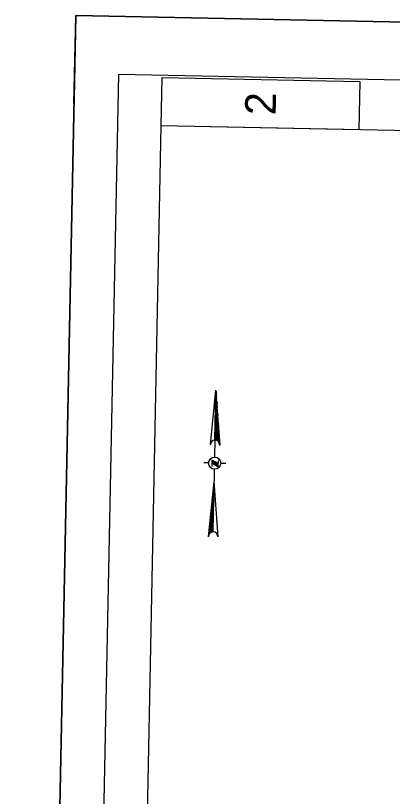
# Model space of a CAD drawing. Extents: x 345549 to 379569, y 127949 to 230467.
# Drawn here: x 345549 to 351986, y 217135 to 230467 of the extents above; entities that cross this region are included whole.
import ezdxf

# ---------------------------------------------------------------- set-up
doc = ezdxf.new("R2010")
doc.units = 0
for name, color, linetype in [('CA-TBLK', 7, 'Continuous'), ('P_RDWY_Text', 7, 'Continuous'), ('PLT_Sheet_Border', 7, 'Continuous'), ('PLT_Sheet_Info', 7, 'Continuous')]:
    doc.layers.add(name, color=color, linetype=linetype)

msp = doc.modelspace()

# ---------------------------------------------------------------- linework, layer by layer
at = {"layer": 'CA-TBLK'}
for p, q in [((348878, 223145), (348971, 224073)), ((348954, 223218), (348971, 224073)), ((348969, 223968), (348985, 223983)), ((348985, 224028), (348970, 224013)), ((348970, 224028), (348985, 224028)), ((348970, 224013), (348985, 224013)), ((348970, 223983), (348985, 223998)), ((348985, 223998), (348970, 223998)), ((348985, 223983), (348970, 223983)), ((349043, 223141), (348971, 224073)), ((348971, 224073), (348971, 224073)), ((348971, 224073), (348971, 224073)), ((348971, 224058), (348971, 224058)), ((348971, 224043), (348986, 224043)), ((348986, 224043), (348971, 224043)), ((348966, 223833), (348997, 223847)), ((348997, 223847), (348966, 223818)), ((348967, 223878), (348983, 223893)), ((348983, 223893), (348967, 223878)), ((348982, 223878), (348967, 223863)), ((348967, 223848), (348997, 223877)), ((348997, 223862), (348967, 223848)), ((348984, 223938), (348968, 223923)), ((348983, 223923), (348968, 223908)), ((348968, 223908), (348983, 223923)), ((348968, 223893), (348983, 223908)), ((348984, 223968), (348969, 223953)), ((348984, 223953), (348969, 223938)), ((348969, 223953), (348984, 223953)), ((348969, 223938), (348984, 223938)), ((348994, 223712), (348963, 223683)), ((348964, 223728), (348995, 223757)), ((348964, 223713), (348995, 223742)), ((348995, 223742), (348964, 223728)), ((348994, 223727), (348964, 223698)), ((348964, 223698), (348994, 223727)), ((348965, 223773), (348996, 223802)), ((348996, 223787), (348965, 223773)), ((348965, 223758), (348996, 223787)), ((348995, 223772), (348965, 223743)), ((348996, 223832), (348966, 223803)), ((348966, 223818), (348996, 223832)), ((348966, 223788), (348996, 223817)), ((348996, 223802), (348966, 223788)), ((348960, 223533), (349006, 223577)), ((348961, 223578), (349007, 223607)), ((349007, 223607), (348961, 223563)), ((349007, 223592), (348961, 223548)), ((348961, 223563), (349007, 223592)), ((348962, 223608), (349008, 223652)), ((349008, 223652), (348962, 223623)), ((348962, 223593), (349008, 223637)), ((349008, 223637), (348962, 223608)), ((349007, 223622), (348962, 223593)), ((348994, 223697), (348963, 223668)), ((348963, 223668), (348994, 223697)), ((349008, 223682), (348963, 223638)), ((348963, 223653), (349008, 223682)), ((348963, 223638), (349008, 223667)), ((348958, 223428), (349019, 223472)), ((349019, 223472), (348958, 223428)), ((348958, 223398), (349019, 223457)), ((349019, 223457), (348958, 223413)), ((349019, 223442), (348958, 223398)), ((349005, 223517), (348959, 223473)), ((348959, 223473), (349005, 223517)), ((349020, 223502), (348959, 223443)), ((348959, 223458), (349020, 223502)), ((348959, 223443), (349020, 223487)), ((348960, 223518), (349006, 223562)), ((349006, 223562), (348960, 223533)), ((348960, 223503), (349006, 223547)), ((349006, 223547), (348960, 223503)), ((349005, 223532), (348960, 223488)), ((349017, 223337), (348955, 223278)), ((348955, 223278), (349017, 223337)), ((349031, 223321), (348955, 223248)), ((348955, 223263), (349031, 223321)), ((348955, 223248), (349031, 223306)), ((348956, 223323), (349017, 223382)), ((348956, 223308), (349017, 223367)), ((349017, 223367), (348956, 223308)), ((349017, 223352), (348956, 223293)), ((349018, 223427), (348957, 223368)), ((348957, 223383), (349018, 223427)), ((349018, 223412), (348957, 223353)), ((348957, 223368), (349018, 223412)), ((348957, 223338), (349018, 223397)), ((349017, 223382), (348957, 223338)), ((348954, 223218), (348948, 222933)), ((348954, 223233), (349031, 223291)), ((349031, 223291), (348954, 223233)), ((349030, 223276), (348954, 223218)), ((348969, 223218), (349030, 223276)), ((349030, 223261), (348984, 223217)), ((348984, 223217), (349030, 223246)), ((349030, 223246), (348999, 223202)), ((349029, 223231), (348999, 223202)), ((348999, 223202), (349029, 223231)), ((349029, 223201), (349013, 223187)), ((349013, 223187), (349029, 223201)), ((349014, 223202), (349029, 223216)), ((349028, 223171), (349028, 223186)), ((349028, 223186), (349028, 223186)), ((349028, 223171), (349028, 223171)), ((349028, 223156), (349028, 223156)), ((349028, 223156), (349028, 223156)), ((349028, 223141), (349043, 223141)), ((348841, 222830), (348766, 222832)), ((348902, 222874), (348900, 222769)), ((348901, 222829), (348947, 222858)), ((348932, 222858), (348901, 222829)), ((348901, 222829), (348932, 222858)), ((348901, 222829), (349005, 222767)), ((348902, 222859), (348917, 222874)), ((348917, 222874), (348902, 222859)), ((348902, 222874), (348902, 222874)), ((349006, 222827), (348902, 222874)), ((348932, 222873), (348902, 222844)), ((348947, 222858), (348916, 222814)), ((348916, 222814), (348962, 222843)), ((348962, 222843), (348931, 222813)), ((348931, 222813), (348977, 222842)), ((348946, 222798), (348977, 222842)), ((348977, 222842), (348946, 222813)), ((349006, 222827), (348961, 222798)), ((348961, 222798), (348991, 222827)), ((348991, 222827), (348961, 222798)), ((348975, 222782), (349006, 222812)), ((349006, 222812), (348975, 222782)), ((348990, 222782), (349006, 222797)), ((349006, 222797), (348990, 222782)), ((349007, 222872), (349005, 222767)), ((349005, 222767), (349005, 222782)), ((349051, 222826), (349141, 222824)), ((348944, 222723), (348940, 222513)), ((348846, 221570), (348940, 222513)), ((348923, 221658), (348940, 222513)), ((349011, 221567), (348940, 222513)), ((348940, 222513), (348940, 222513)), ((348937, 222378), (348938, 222393)), ((348937, 222363), (348937, 222378)), ((348937, 222378), (348937, 222378)), ((348938, 222438), (348939, 222453)), ((348938, 222438), (348938, 222438)), ((348938, 222423), (348938, 222423)), ((348938, 222423), (348938, 222408)), ((348938, 222408), (348938, 222393)), ((348938, 222408), (348938, 222408)), ((348939, 222483), (348939, 222483)), ((348939, 222468), (348939, 222468)), ((348939, 222468), (348939, 222468)), ((348939, 222453), (348939, 222453)), ((348940, 222498), (348940, 222498)), ((348940, 222498), (348940, 222498)), ((348919, 222243), (348934, 222213)), ((348934, 222228), (348919, 222243)), ((348935, 222273), (348920, 222288)), ((348920, 222288), (348935, 222273)), ((348934, 222243), (348920, 222273)), ((348920, 222273), (348935, 222258)), ((348920, 222258), (348934, 222243)), ((348936, 222333), (348921, 222333)), ((348921, 222333), (348936, 222318)), ((348921, 222318), (348935, 222288)), ((348936, 222303), (348921, 222318)), ((348935, 222288), (348921, 222303)), ((348922, 222348), (348936, 222333)), ((348937, 222363), (348937, 222348)), ((348937, 222348), (348937, 222363)), ((348902, 222139), (348932, 222108)), ((348932, 222108), (348902, 222139)), ((348931, 222093), (348902, 222124)), ((348931, 222078), (348902, 222109)), ((348902, 222109), (348931, 222078)), ((348903, 222169), (348932, 222138)), ((348903, 222154), (348932, 222123)), ((348932, 222138), (348903, 222154)), ((348933, 222153), (348918, 222184)), ((348918, 222184), (348933, 222153)), ((348919, 222228), (348934, 222198)), ((348934, 222213), (348919, 222228)), ((348919, 222214), (348933, 222183)), ((348933, 222183), (348919, 222214)), ((348933, 222168), (348919, 222199)), ((348884, 221989), (348928, 221943)), ((348884, 221974), (348928, 221928)), ((348928, 221928), (348884, 221974)), ((348929, 221958), (348885, 222004)), ((348929, 221988), (348900, 222034)), ((348929, 221973), (348900, 222019)), ((348900, 222019), (348929, 221988)), ((348900, 222004), (348929, 221958)), ((348931, 222048), (348901, 222094)), ((348901, 222094), (348931, 222063)), ((348901, 222079), (348931, 222048)), ((348901, 222064), (348930, 222018)), ((348930, 222033), (348901, 222064)), ((348930, 222018), (348901, 222049)), ((348901, 222049), (348930, 222003)), ((348882, 221884), (348926, 221823)), ((348926, 221838), (348882, 221884)), ((348882, 221869), (348926, 221808)), ((348926, 221823), (348882, 221869)), ((348925, 221793), (348882, 221854)), ((348928, 221898), (348883, 221944)), ((348883, 221929), (348927, 221883)), ((348927, 221883), (348883, 221929)), ((348927, 221853), (348883, 221914)), ((348883, 221914), (348927, 221868)), ((348883, 221899), (348927, 221853)), ((348884, 221959), (348928, 221913)), ((348928, 221913), (348884, 221959)), ((348923, 221658), (348864, 221735)), ((348864, 221735), (348923, 221673)), ((348864, 221720), (348923, 221658)), ((348865, 221794), (348924, 221733)), ((348924, 221733), (348865, 221794)), ((348865, 221779), (348924, 221703)), ((348924, 221718), (348865, 221779)), ((348924, 221703), (348865, 221764)), ((348923, 221688), (348865, 221750)), ((348865, 221750), (348923, 221688)), ((348925, 221778), (348881, 221839)), ((348881, 221839), (348925, 221793)), ((348925, 221763), (348881, 221824)), ((348881, 221824), (348925, 221763)), ((348881, 221809), (348925, 221748)), ((348846, 221585), (348846, 221585)), ((348847, 221630), (348862, 221615)), ((348847, 221615), (348862, 221615)), ((348862, 221615), (348847, 221615)), ((348847, 221600), (348847, 221600)), ((348847, 221600), (348847, 221600)), ((348862, 221645), (348877, 221629)), ((348862, 221630), (348862, 221645)), ((348863, 221690), (348892, 221644)), ((348907, 221644), (348863, 221690)), ((348892, 221644), (348863, 221675)), ((348877, 221629), (348863, 221660)), ((348863, 221660), (348877, 221644)), ((348864, 221705), (348908, 221659)), ((348923, 221658), (348864, 221705))]:
    msp.add_line(p, q, dxfattribs=at)
msp.add_circle((348950, 222826), 104, dxfattribs=at)
for centre, start, end in [((348956, 223139), 358.8468, 178.8468), ((348956, 223139), 178.84682431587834, 178.8468298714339), ((348924, 221574), 358.8468, 178.8468), ((348924, 221574), 358.84700764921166, 358.8470132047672)]:
    msp.add_arc(centre, 78.3, start, end, dxfattribs=at)
at = {"layer": 'P_RDWY_Text'}
msp.add_lwpolyline([(345549, 179477), (346576, 230467), (379569, 229803), (378542, 178813)], close=True, dxfattribs=at)
at = {"layer": 'PLT_Sheet_Border'}
for points in [[(378542, 178813), (379569, 229803), (346576, 230467), (345549, 179477)], [(377800, 179188), (378799, 228828), (347306, 229462), (346306, 179822)]]:
    msp.add_lwpolyline(points, close=True, dxfattribs=at)
at = {"layer": 'PLT_Sheet_Info'}
for p, q in [((346546, 228967), (346576, 230467)), ((348076, 230437), (346576, 230467)), ((347087, 181344), (348038, 228585)), ((378032, 227981), (348038, 228585))]:
    msp.add_line(p, q, dxfattribs=at)
msp.add_lwpolyline([(348038, 228585), (348055, 229410), (351429, 229342), (351413, 228517)], close=True, dxfattribs=at)

# ---------------------------------------------------------------- texts
msp.add_text('2', height=525, rotation=88.8462, dxfattribs=at).set_placement((349992, 228762))

doc.saveas('drawing.dxf')
